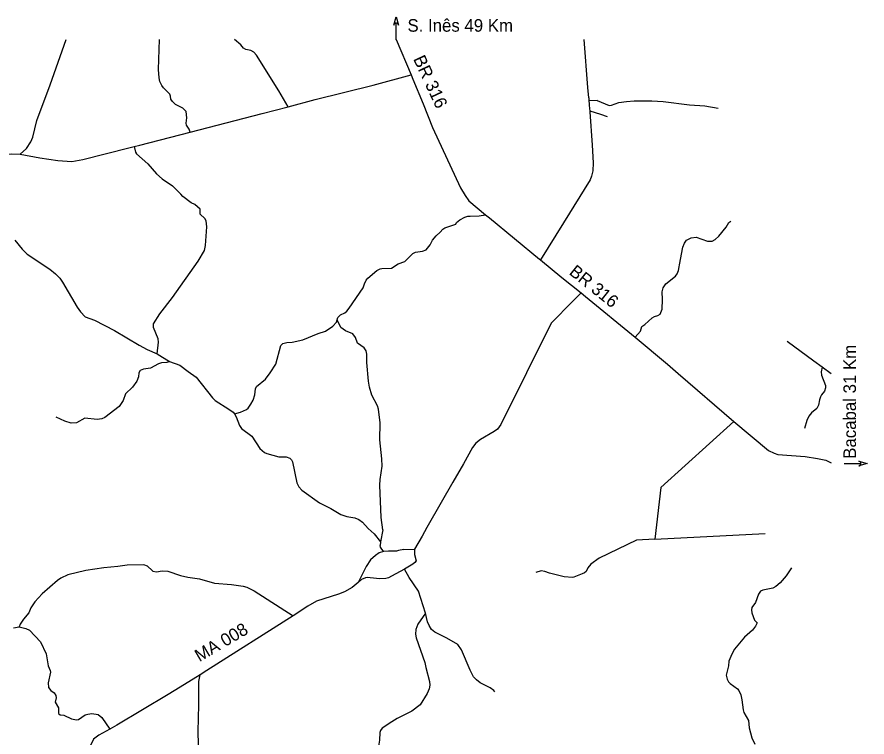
# Model space of a CAD drawing. Extents: x 332 to 501, y 9447 to 9559.
# Drawn here: x 475.39 to 501.08, y 9536.78 to 9558.55 of the extents above; entities that cross this region are included whole.
import ezdxf

# ---------------------------------------------------------------- set-up
doc = ezdxf.new("R2010")
doc.units = 0
for name, color, linetype in [('Level 12', 7, 'Continuous'), ('Level 2', 7, 'Continuous'), ('Level 31', 7, 'Continuous'), ('Level 4', 7, 'Continuous'), ('Level 5', 7, 'Continuous'), ('Level 6', 7, 'Continuous'), ('Level 7', 7, 'Continuous'), ('Level 8', 7, 'Continuous')]:
    doc.layers.add(name, color=color, linetype=linetype)

msp = doc.modelspace()

# ---------------------------------------------------------------- linework, layer by layer
at = {"layer": 'Level 12'}
for p, q in [((486.8476, 9557.863), (486.8476, 9558.363)), ((500.3918, 9545.0479), (500.8918, 9545.0479))]:
    msp.add_line(p, q, dxfattribs=at)
for points in [[(486.9214, 9558.3093), (486.9126, 9558.328), (486.9026, 9558.3405), (486.8839, 9558.3543), (486.8564, 9558.363), (486.8476, 9558.363), (486.8276, 9558.3605), (486.8101, 9558.3543), (486.7951, 9558.343), (486.7826, 9558.328), (486.7739, 9558.3093), (486.8476, 9558.5518)], [(500.8381, 9544.9742), (500.8568, 9544.9829), (500.8693, 9544.9929), (500.8831, 9545.0117), (500.8918, 9545.0392), (500.8918, 9545.0479), (500.8893, 9545.0679), (500.8831, 9545.0854), (500.8718, 9545.1004), (500.8568, 9545.1129), (500.8381, 9545.1217), (501.0806, 9545.0479)]]:
    msp.add_lwpolyline(points, close=True, dxfattribs=at)
at = {"layer": 'Level 2'}
for points in [[(486.8438, 9557.8716), (487.3053, 9556.8022)], [(487.3053, 9556.8022), (487.3571, 9556.6706)], [(487.3571, 9556.6706), (487.661, 9555.9224)], [(487.661, 9555.9224), (487.9508, 9555.2104), (488.7939, 9553.3867), (488.9302, 9553.1494), (489.0476, 9552.9941), (489.5497, 9552.5734)], [(489.5497, 9552.5734), (489.6653, 9552.4795)], [(489.6653, 9552.4795), (491.1817, 9551.2278)], [(491.1817, 9551.2278), (491.2111, 9551.2038)], [(491.2111, 9551.2038), (491.8595, 9550.6746)], [(491.8595, 9550.6746), (492.4398, 9550.2115)], [(492.4398, 9550.2115), (492.1921, 9549.9614)], [(492.4398, 9550.2115), (492.5762, 9550.0952)], [(492.5762, 9550.0952), (494.0708, 9548.8741)], [(492.1921, 9549.9614), (491.5302, 9549.2935), (490.7887, 9547.7949)], [(494.0708, 9548.8741), (495.047, 9548.0491)], [(495.047, 9548.0491), (495.3694, 9547.7682)], [(490.7887, 9547.7949), (490.0119, 9546.2253), (489.9071, 9546.0927), (489.8135, 9546.0191)], [(495.3694, 9547.7682), (497.0528, 9546.3212)], [(497.0528, 9546.3212), (498.1047, 9545.444), (498.2713, 9545.3619), (498.3874, 9545.3216), (499.2078, 9545.2572), (499.5793, 9545.1993), (499.8354, 9545.1526), (500, 9545.0718)], [(489.8135, 9546.0191), (489.4022, 9545.7747), (489.2609, 9545.6661), (489.1586, 9545.5285), (488.8837, 9545.0413)], [(488.8837, 9545.0413), (488.5608, 9544.4803)], [(488.5608, 9544.4803), (487.812, 9543.184)], [(487.7712, 9543.1109), (487.6294, 9542.8572)], [(487.812, 9543.184), (487.7712, 9543.1109)], [(487.6294, 9542.8572), (487.4062, 9542.4577)], [(487.0989, 9541.8582), (486.7048, 9541.6438)], [(486.256, 9541.5705), (485.9731, 9541.5983), (485.9175, 9541.5907), (485.8026, 9541.537), (485.6978, 9541.4491)], [(486.7048, 9541.6438), (486.6142, 9541.5919), (486.5385, 9541.5704), (486.3593, 9541.5604), (486.256, 9541.5705)], [(485.6978, 9541.4491), (485.5162, 9541.2966), (485.2839, 9541.1679)], [(485.2839, 9541.1679), (485.1034, 9541.0972), (484.4408, 9540.8915), (484.1827, 9540.7316)], [(484.1827, 9540.7316), (483.7339, 9540.4458)], [(483.7339, 9540.4458), (481.1239, 9538.7874)], [(481.1239, 9538.7874), (480.9213, 9538.6584)], [(480.9213, 9538.6584), (480.3204, 9538.2883)], [(480.3204, 9538.2883), (479.9525, 9538.0636)], [(479.9525, 9538.0636), (478.4027, 9537.1402)], [(478.4027, 9537.1402), (478.1886, 9537.0149)], [(478.1886, 9537.0149), (477.8575, 9536.8299), (477.7009, 9536.7176), (477.3422, 9535.9814)]]:
    msp.add_lwpolyline(points, dxfattribs=at)
at = {"layer": 'Level 4'}
for points in [[(476.3876, 9556.5005), (476.8743, 9557.8697)], [(475.4843, 9554.4041), (475.6765, 9554.5743), (475.8027, 9554.7725), (475.8645, 9554.9214), (475.9872, 9555.419), (476.3876, 9556.5005)], [(492.6863, 9555.863), (492.6906, 9555.8005)], [(492.6906, 9555.8005), (492.6985, 9555.6874)], [(492.6985, 9555.6874), (492.6985, 9555.6866)], [(492.6985, 9555.6866), (492.7689, 9554.6749)], [(492.7689, 9554.6749), (492.8062, 9554.1389), (492.7936, 9553.9025)], [(474.0144, 9553.692), (474.2718, 9554.0039), (474.4237, 9554.1407), (474.5759, 9554.2435), (474.7142, 9554.3066), (474.9932, 9554.3943), (475.2272, 9554.4141), (475.4843, 9554.4041)], [(492.7936, 9553.9025), (492.7558, 9553.7376), (492.709, 9553.6265), (491.9083, 9552.3224)], [(491.9083, 9552.3224), (491.2111, 9551.2038)], [(475.2827, 9540.079), (475.4518, 9540.1152)], [(475.4518, 9540.1152), (475.6588, 9540.056), (475.7629, 9540.0073), (476.1018, 9539.6609), (476.2722, 9539.2924), (476.3252, 9538.9319)], [(476.3252, 9538.9319), (476.3946, 9538.7888), (476.4047, 9538.7358), (476.3277, 9538.4127), (476.3403, 9538.2789), (476.4072, 9538.1804), (476.5108, 9538.111), (476.5612, 9538.0353), (476.5701, 9537.9595), (476.5448, 9537.8321), (476.6458, 9537.6579), (476.6458, 9537.4888), (476.6937, 9537.4484), (476.8074, 9537.4383), (477.0396, 9537.326), (477.1885, 9537.3032), (477.2466, 9537.3108), (477.4434, 9537.4446), (477.5293, 9537.4736), (477.6454, 9537.4863), (477.8423, 9537.4597), (477.9483, 9537.3726), (478.1886, 9537.0149)]]:
    msp.add_lwpolyline(points, dxfattribs=at)
at = {"layer": 'Level 5'}
for points in [[(480.0845, 9555.9975), (480.0362, 9556.0694), (480.0299, 9556.1601), (480.0096, 9556.2149), (479.8112, 9556.412), (479.762, 9556.4839), (479.7052, 9556.6051), (479.6812, 9556.7086), (479.6648, 9556.9661), (479.6901, 9557.8703)], [(483.5817, 9555.8365), (483.3036, 9556.3199), (482.6218, 9557.4006), (482.5413, 9557.4848), (482.4542, 9557.5404), (482.3078, 9557.5719), (482.2296, 9557.6085), (482.1551, 9557.7082), (481.9584, 9557.8708)], [(492.6427, 9556.4239), (492.5335, 9557.8722)], [(483.5817, 9555.8365), (484.402, 9556.0588), (486.1523, 9556.4902), (487.3053, 9556.8022)], [(492.6709, 9556.1079), (492.6427, 9556.4239)], [(480.6195, 9555.0671), (480.588, 9555.16), (480.5082, 9555.2836), (480.502, 9555.3399), (480.5243, 9555.5071), (480.4992, 9555.6939), (480.4007, 9555.7909), (480.1832, 9555.9035), (480.0845, 9555.9975)], [(492.6709, 9556.1079), (492.6728, 9556.0433)], [(492.6728, 9556.0433), (492.6749, 9556.0155)], [(492.9242, 9556.0258), (492.6749, 9556.0155)], [(492.6749, 9556.0155), (492.6817, 9555.9246)], [(492.6817, 9555.9246), (492.6863, 9555.863)], [(480.6195, 9555.0671), (482.7969, 9555.6292)], [(482.7969, 9555.6292), (483.5817, 9555.8365)], [(479.0998, 9554.6739), (480.6195, 9555.0671)], [(478.7725, 9554.5917), (478.9323, 9554.6318)], [(478.9323, 9554.6318), (479.0998, 9554.6739)], [(478.9323, 9554.6318), (478.9698, 9554.4613), (478.998, 9554.4159), (479.3405, 9554.1124), (479.6054, 9553.8063)], [(475.4843, 9554.4041), (476.0755, 9554.2891), (476.6206, 9554.2159), (477.0497, 9554.1793), (477.3753, 9554.2424), (478.7725, 9554.5917)], [(479.6054, 9553.8063), (479.7784, 9553.6605), (480.0843, 9553.4489), (480.3346, 9553.197)], [(489.0857, 9552.5297), (489.3533, 9552.5391), (489.5497, 9552.5734)], [(485.8934, 9550.4861), (485.9466, 9550.5925), (485.9958, 9550.6516), (486.2595, 9550.8851), (486.3643, 9550.9356), (486.4199, 9550.9457), (486.7076, 9550.9609), (486.907, 9551.0858), (487.1115, 9551.159), (487.3538, 9551.3976), (487.4371, 9551.4354), (487.6441, 9551.472), (487.7514, 9551.5137), (487.8726, 9551.6576), (487.9508, 9551.8052), (488.0541, 9551.9382), (488.1824, 9552.0431), (488.259, 9552.1338), (488.3232, 9552.1737), (488.6535, 9552.2899)], [(488.6535, 9552.2899), (488.6754, 9552.3384), (488.7724, 9552.4213), (488.9214, 9552.4968), (489.0122, 9552.5266), (489.0857, 9552.5297)], [(475.3226, 9551.8001), (475.5446, 9551.5336)], [(475.5446, 9551.5336), (475.6992, 9551.3824), (476.3765, 9550.9214)], [(476.3765, 9550.9214), (476.5536, 9550.786), (476.6786, 9550.6491), (476.7645, 9550.533), (477.2099, 9549.7807), (477.3071, 9549.6381), (477.4472, 9549.4803), (477.7287, 9549.3831), (478.3357, 9549.0688), (479.0751, 9548.6279)], [(479.0751, 9548.6279), (479.319, 9548.492), (479.6198, 9548.3619)], [(479.6198, 9548.3619), (479.9955, 9548.1298)], [(479.9955, 9548.1298), (480.3123, 9548.0234)], [(480.3123, 9548.0234), (480.5584, 9547.8306), (480.8034, 9547.6653), (481.2918, 9547.0317), (481.3776, 9546.9534), (481.7904, 9546.6973), (481.9191, 9546.6026), (481.9606, 9546.553)], [(486.4488, 9543.0433), (486.3958, 9543.4157), (486.3593, 9544.3926), (486.3656, 9544.5643), (486.4249, 9544.9656), (486.4173, 9545.1954), (486.3593, 9545.7684), (486.363, 9546.2808), (486.3161, 9546.6955)], [(481.9606, 9546.553), (482.0137, 9546.4651), (482.1147, 9546.2025), (482.174, 9546.1041), (482.487, 9545.8719), (482.7294, 9545.5071), (482.8657, 9545.3834)], [(482.8657, 9545.3834), (482.9364, 9545.3506), (483.2999, 9545.2559), (483.5271, 9545.2496), (483.6381, 9545.2105), (483.6835, 9545.1625), (483.71, 9545.0994), (483.8489, 9544.4684), (483.9106, 9544.3458), (483.9984, 9544.2474), (484.5278, 9543.8561), (484.8725, 9543.6921), (485.1754, 9543.5091), (485.3571, 9543.4498), (485.5995, 9543.4031), (485.7206, 9543.3577), (485.8355, 9543.2731), (485.9983, 9543.0813), (486.1825, 9542.9216), (486.3767, 9542.6789)], [(479.4945, 9541.7965), (479.5992, 9541.7762), (479.7784, 9541.804), (479.9476, 9541.7914), (480.3287, 9541.6639), (480.5559, 9541.6121), (480.9018, 9541.5655), (481.3587, 9541.4317), (481.8737, 9541.3862), (482.2195, 9541.3408), (482.3306, 9541.3117), (482.5603, 9541.1982), (483.7339, 9540.4458)], [(487.7302, 9540.5209), (487.5267, 9541.1894), (487.239, 9541.6033), (487.0989, 9541.8582)]]:
    msp.add_lwpolyline(points, dxfattribs=at)
at = {"layer": 'Level 6'}
for points in [[(479.6198, 9548.3619), (479.6612, 9548.7192), (479.655, 9548.8148), (479.5171, 9549.1666), (479.5124, 9549.2716), (479.702, 9549.5717), (480.0875, 9550.0646), (480.8632, 9551.1703), (481.0544, 9551.4876), (481.0826, 9551.6443), (481.1217, 9552.2061), (481.106, 9552.3871), (481.0622, 9552.4545), (480.9227, 9552.5932), (480.9227, 9552.7405), (480.7628, 9552.88), (480.6563, 9552.9348), (480.3962, 9553.1237), (480.3346, 9553.197)], [(495.4149, 9551.0602), (495.511, 9551.5945), (495.5614, 9551.7156), (495.6283, 9551.8014), (495.7684, 9551.8777), (495.9212, 9551.8935), (496.2619, 9551.7736), (496.4033, 9551.7724), (496.4866, 9551.8204), (496.606, 9551.9271), (496.8218, 9552.1962), (496.9081, 9552.3404), (496.9675, 9552.3807)], [(494.0708, 9548.8741), (494.2324, 9549.0512), (494.2741, 9549.1963), (494.3675, 9549.2569), (494.5896, 9549.4525), (494.6546, 9549.4947), (494.7587, 9549.5219), (494.8256, 9549.5623), (494.8849, 9549.7189), (494.9001, 9550.0042), (494.8912, 9550.2415), (494.9228, 9550.3576), (494.9973, 9550.4837), (495.2951, 9550.7173), (495.3431, 9550.7841), (495.386, 9550.8902), (495.4039, 9550.9989)], [(495.4039, 9550.9989), (495.4149, 9551.0602)], [(485.0653, 9549.3928), (485.0826, 9549.4647), (485.1625, 9549.5446), (485.2941, 9549.6026), (485.3599, 9549.6513), (485.432, 9549.7453), (485.8487, 9550.3643), (485.8934, 9550.4861)], [(483.3943, 9548.652), (483.4248, 9548.6788), (483.5423, 9548.7063), (483.7068, 9548.7172), (484.0311, 9548.788), (484.4902, 9548.9823), (484.7158, 9549.0489), (484.9383, 9549.2041), (485.0433, 9549.3225), (485.0653, 9549.3928)], [(486.3161, 9546.6955), (486.2887, 9546.7904), (486.1179, 9547.1164), (486.0474, 9547.3554), (486.0129, 9547.5403), (485.96, 9548.1063), (485.9663, 9548.3602), (485.9459, 9548.4534), (485.8848, 9548.5459), (485.6827, 9548.6916), (485.62, 9548.8592), (485.5354, 9548.9658), (485.3207, 9549.0661), (485.1719, 9549.1672), (485.0653, 9549.3928)], [(499.4779, 9548.1416), (498.664, 9548.7358)], [(481.9606, 9546.553), (482.1408, 9546.6051), (482.328, 9546.6854), (482.3797, 9546.7269), (482.4581, 9546.8413), (482.527, 9546.9678), (482.5811, 9547.1241), (482.5952, 9547.3117), (482.625, 9547.3736), (482.8952, 9547.6038), (483.0363, 9547.7871), (483.207, 9548.0559), (483.3605, 9548.6223), (483.3943, 9548.652)], [(479.9955, 9548.1298), (479.9122, 9548.1051), (479.7597, 9548.0947), (479.6636, 9548.0654), (479.4254, 9547.9317), (479.206, 9547.9004), (479.1057, 9547.8586), (479.0723, 9547.7959), (479.0577, 9547.6685), (479.0117, 9547.5347), (478.8823, 9547.3586), (478.669, 9547.1517), (478.592, 9546.956), (478.4768, 9546.7718), (478.043, 9546.441), (477.9559, 9546.4044), (477.8095, 9546.3817), (477.4334, 9546.4221), (477.1837, 9546.2826), (477.0198, 9546.272), (476.8294, 9546.3302), (476.5729, 9546.4535)], [(499.7216, 9547.9659), (499.696, 9547.819), (499.7069, 9547.7208), (499.8231, 9547.413), (499.8271, 9547.3356), (499.7954, 9547.2414), (499.7021, 9547.1282), (499.6723, 9547.0656), (499.6415, 9546.9773), (499.6167, 9546.8145), (499.5691, 9546.7153), (499.4003, 9546.5774), (499.3259, 9546.4811), (499.2634, 9546.3481), (499.1959, 9546.105)], [(499.7216, 9547.9659), (499.4779, 9548.1416)], [(500, 9547.7623), (499.7216, 9547.9659)], [(497.0528, 9546.3212), (494.8445, 9544.3194), (494.6666, 9542.7569)], [(494.6666, 9542.7569), (498.0062, 9542.9336)], [(494.6666, 9542.7569), (494.1138, 9542.7278), (492.9806, 9542.1857)], [(492.9806, 9542.1857), (492.733, 9542.0072), (492.6434, 9541.8973), (492.5905, 9541.787), (492.5386, 9541.7446), (492.4667, 9541.7143)], [(479.4693, 9541.8173), (479.336, 9541.9407), (479.22, 9541.9893), (478.7154, 9541.9791), (478.4397, 9541.9314), (478.0119, 9541.8946), (477.4725, 9541.8111), (476.9235, 9541.6828), (476.7077, 9541.5793), (476.6143, 9541.5124), (476.15, 9541.1126), (475.9213, 9540.8705), (475.8084, 9540.6809), (475.7426, 9540.5328), (475.5871, 9540.3434), (475.4814, 9540.1916), (475.4518, 9540.1152)], [(479.4945, 9541.7965), (479.4693, 9541.8173)], [(492.2218, 9541.6117), (492.1752, 9541.5982), (491.9228, 9541.6235), (491.4861, 9541.732), (491.3409, 9541.7888), (491.2336, 9541.8002), (491.0733, 9541.7497)], [(498.7938, 9541.8986), (498.6372, 9541.6512), (498.453, 9541.4392), (498.3242, 9541.3282), (498.2385, 9541.2789), (497.933, 9541.2196), (497.8648, 9541.1843), (497.7967, 9541.0997), (497.7083, 9540.8485), (497.6035, 9540.6958), (497.5935, 9540.6214), (497.6036, 9540.5381), (497.6831, 9540.3083), (497.7563, 9540.2301)], [(492.4667, 9541.7143), (492.2218, 9541.6117)], [(487.7302, 9540.5209), (487.5077, 9540.1903), (487.445, 9540.0336), (487.4325, 9539.8878), (487.4497, 9539.7758), (487.7145, 9539.0369), (487.7443, 9538.8763), (487.8586, 9538.4618), (487.8633, 9538.3505), (487.843, 9538.2361), (487.7866, 9538.0927), (487.5751, 9537.7503)], [(489.8347, 9538.1481), (489.8051, 9538.1839), (489.686, 9538.2639), (489.3899, 9538.4198), (489.2739, 9538.5076), (489.1862, 9538.6001), (489.0843, 9538.7975), (488.8273, 9539.4198), (488.7129, 9539.5718), (488.3822, 9539.7702), (488.0186, 9539.9481), (487.9183, 9540.0281), (487.8446, 9540.1519), (487.7992, 9540.2647), (487.7302, 9540.5209)], [(496.9068, 9539.074), (496.8942, 9538.9276), (496.8273, 9538.6474), (496.8488, 9538.5237), (496.8942, 9538.4467), (496.9485, 9538.3949), (497.1681, 9538.2384), (497.2098, 9538.1867), (497.2704, 9538.0504), (497.302, 9537.9015), (497.3335, 9537.6024), (497.3587, 9537.5241), (497.495, 9537.2742), (497.5203, 9537.0597), (497.6023, 9536.7491), (497.6897, 9536.5626)], [(480.6291, 9535.131), (480.8965, 9535.7519), (480.8668, 9536.9428), (480.8872, 9537.7546), (480.8825, 9538.4567), (480.9213, 9538.6584)], [(487.5751, 9537.7503), (487.3227, 9537.5575), (486.8746, 9537.3374), (486.7147, 9537.2418), (486.4295, 9537.0436), (486.3766, 9536.9755)], [(486.3766, 9536.9755), (486.3527, 9536.9198), (486.3496, 9536.6824), (486.3167, 9536.5021), (486.4139, 9536.2162), (486.5267, 9536.0061), (486.9153, 9535.3903), (487.2006, 9535.084), (487.2272, 9535.0401), (487.2382, 9534.91), (487.3095, 9534.8023)]]:
    msp.add_lwpolyline(points, dxfattribs=at)
at = {"layer": 'Level 7'}
for points in [[(492.9242, 9556.0258), (493.2899, 9555.8786), (493.3543, 9555.8811), (493.5789, 9555.9619), (493.8125, 9556.001), (494.0397, 9556.0149), (494.576, 9556.0124), (494.9168, 9555.9973), (495.7183, 9555.8937), (496.1752, 9555.8672), (496.5828, 9555.794)], [(492.7037, 9555.7102), (493.0233, 9555.615), (493.2273, 9555.5402)], [(497.7563, 9540.2301), (497.7096, 9540.1304), (497.6219, 9540.0054), (497.3751, 9539.7959), (497.0785, 9539.4337), (496.9901, 9539.2835), (496.9068, 9539.074)]]:
    msp.add_lwpolyline(points, dxfattribs=at)
at = {"layer": 'Level 8'}
for points in [[(486.4488, 9543.0433), (486.3767, 9542.6789)], [(486.3767, 9542.6789), (486.3612, 9542.572)], [(486.469, 9542.3871), (486.3706, 9542.5233), (486.3612, 9542.572)], [(486.2194, 9542.272), (486.074, 9542.1403), (485.944, 9541.9377), (485.6978, 9541.4491)], [(486.469, 9542.3871), (486.3352, 9542.3499), (486.2194, 9542.272)], [(486.6203, 9542.3953), (486.469, 9542.3871)], [(486.8592, 9542.3937), (486.6203, 9542.3953)], [(486.9237, 9542.4142), (486.8592, 9542.3937)], [(487.0774, 9542.4501), (486.9237, 9542.4142)], [(487.0774, 9542.4501), (487.4062, 9542.4577)], [(487.4017, 9542.2949), (487.4485, 9542.1107), (487.4163, 9542.052), (487.353, 9542.0035)], [(487.4062, 9542.4577), (487.4017, 9542.2949)], [(487.353, 9542.0035), (487.0989, 9541.8582)]]:
    msp.add_lwpolyline(points, dxfattribs=at)

# ---------------------------------------------------------------- texts
at = {"layer": 'Level 12'}
msp.add_text('S. Inês 49 Km', height=0.38, dxfattribs=at).set_placement((487.1894, 9558.1067))
msp.add_text('Bacabal 31 Km', height=0.38, rotation=90, dxfattribs=at).set_placement((500.7477, 9545.1924))
at = {"layer": 'Level 31'}
for s, rotation, p in [('BR 316', 295.01689, (487.3551, 9557.2854)), ('BR 316', 321.34019, (492.0505, 9550.7915)), ('MA 008', 30.48835, (480.9015, 9539.0391))]:
    msp.add_text(s, height=0.38, rotation=rotation, dxfattribs=at).set_placement(p)

doc.saveas('drawing.dxf')
